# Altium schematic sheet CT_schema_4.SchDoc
size 255 x 159 mm
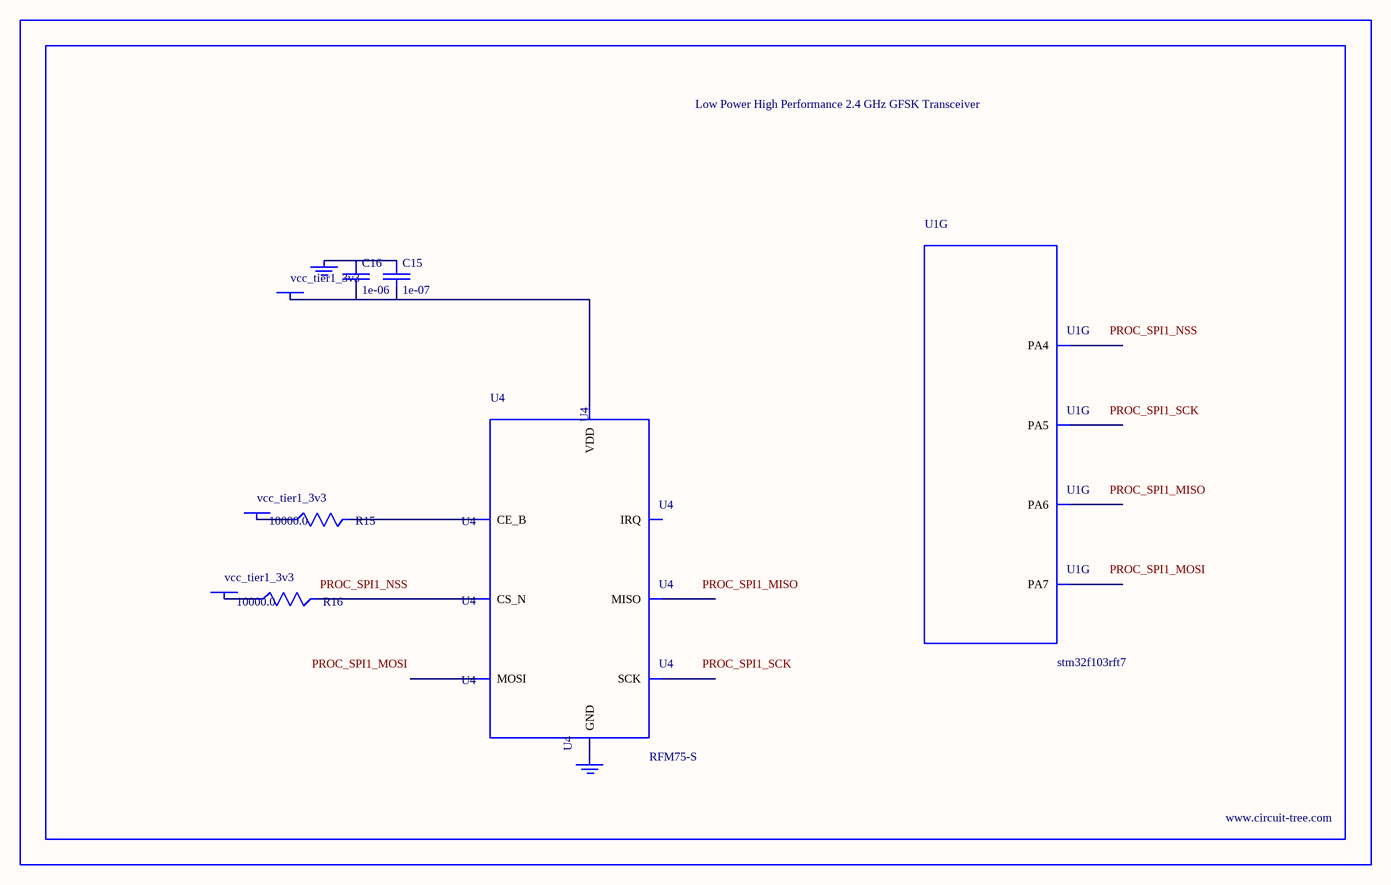
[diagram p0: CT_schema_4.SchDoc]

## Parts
BORDER3  (no value)
C15  1e-07  [C0402]
C16  1e-06  [C0603]
GND_INSTANCE_3_0  (no value)
GND_INSTANCE_3_1  (no value)
POWER_INSTANCE_3_0  vcc_tier1_3v3
POWER_INSTANCE_3_1  vcc_tier1_3v3
POWER_INSTANCE_3_2  vcc_tier1_3v3
R15  10000.0  [R0603]
R16  10000.0  [R0603]
U1  stm32f103rft7  [LQFP64]  (part G of 7)
U4  RFM75-S  [RFM75-S]

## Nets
NetC15_1: C15.1 C16.1 GND_INSTANCE_3_0.0(GND)
NetC15_2: C15.2 C16.2 POWER_INSTANCE_3_0.0(PWR) U4.2(VDD)
NetGND_INSTANCE_3_1_0: GND_INSTANCE_3_1.0(GND) U4.1(GND)
NetPOWER_INSTANCE_3_1_0: POWER_INSTANCE_3_1.0(PWR) R15.1
NetPOWER_INSTANCE_3_2_0: POWER_INSTANCE_3_2.0(PWR) R16.1
NetR15_2: R15.2 U4.3(CE_B)
NetR16_2: R16.2 U4.4(CS_N)

Not connected (* = marked no-connect by the designer): U1 20(PA4) 21(PA5) 22(PA6) 23(PA7); U4 5(SCK) 6(MOSI) 7(MISO) 8(IRQ)

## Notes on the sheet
- Labels drawn without touching a wire or pin: PROC_SPI1_MISO, PROC_SPI1_MOSI, PROC_SPI1_NSS, PROC_SPI1_SCK

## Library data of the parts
BORDER3 = BORDER_PAGE3
C15 = C0402C104K3RACTU
C16 = C0603C105K3RACTU
GND_INSTANCE_3_0 GND_INSTANCE_3_1 = GND
POWER_INSTANCE_3_0-POWER_INSTANCE_3_2 = PWR
R15 R16 = RC0603JR-0710KL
